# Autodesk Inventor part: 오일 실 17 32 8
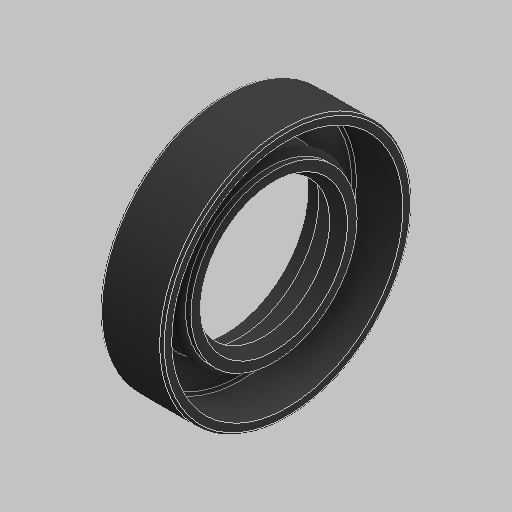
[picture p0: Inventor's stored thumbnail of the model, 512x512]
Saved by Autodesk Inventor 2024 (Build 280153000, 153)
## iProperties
Created: 2026-01
Part Number: 오일 실 17 32 8
Material: 고무
Description: 오일-실
Document SubType Name: Modeling
Designer: 2-10
Density: 0.93 g/cm^3
Appearance: 기본값
Author: jhkim
Sending System: Autodesk Inventor 2026
Preprocessor: ST-DEVELOPER v20.1
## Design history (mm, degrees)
feature "Solid1"
node "솔리드1"
